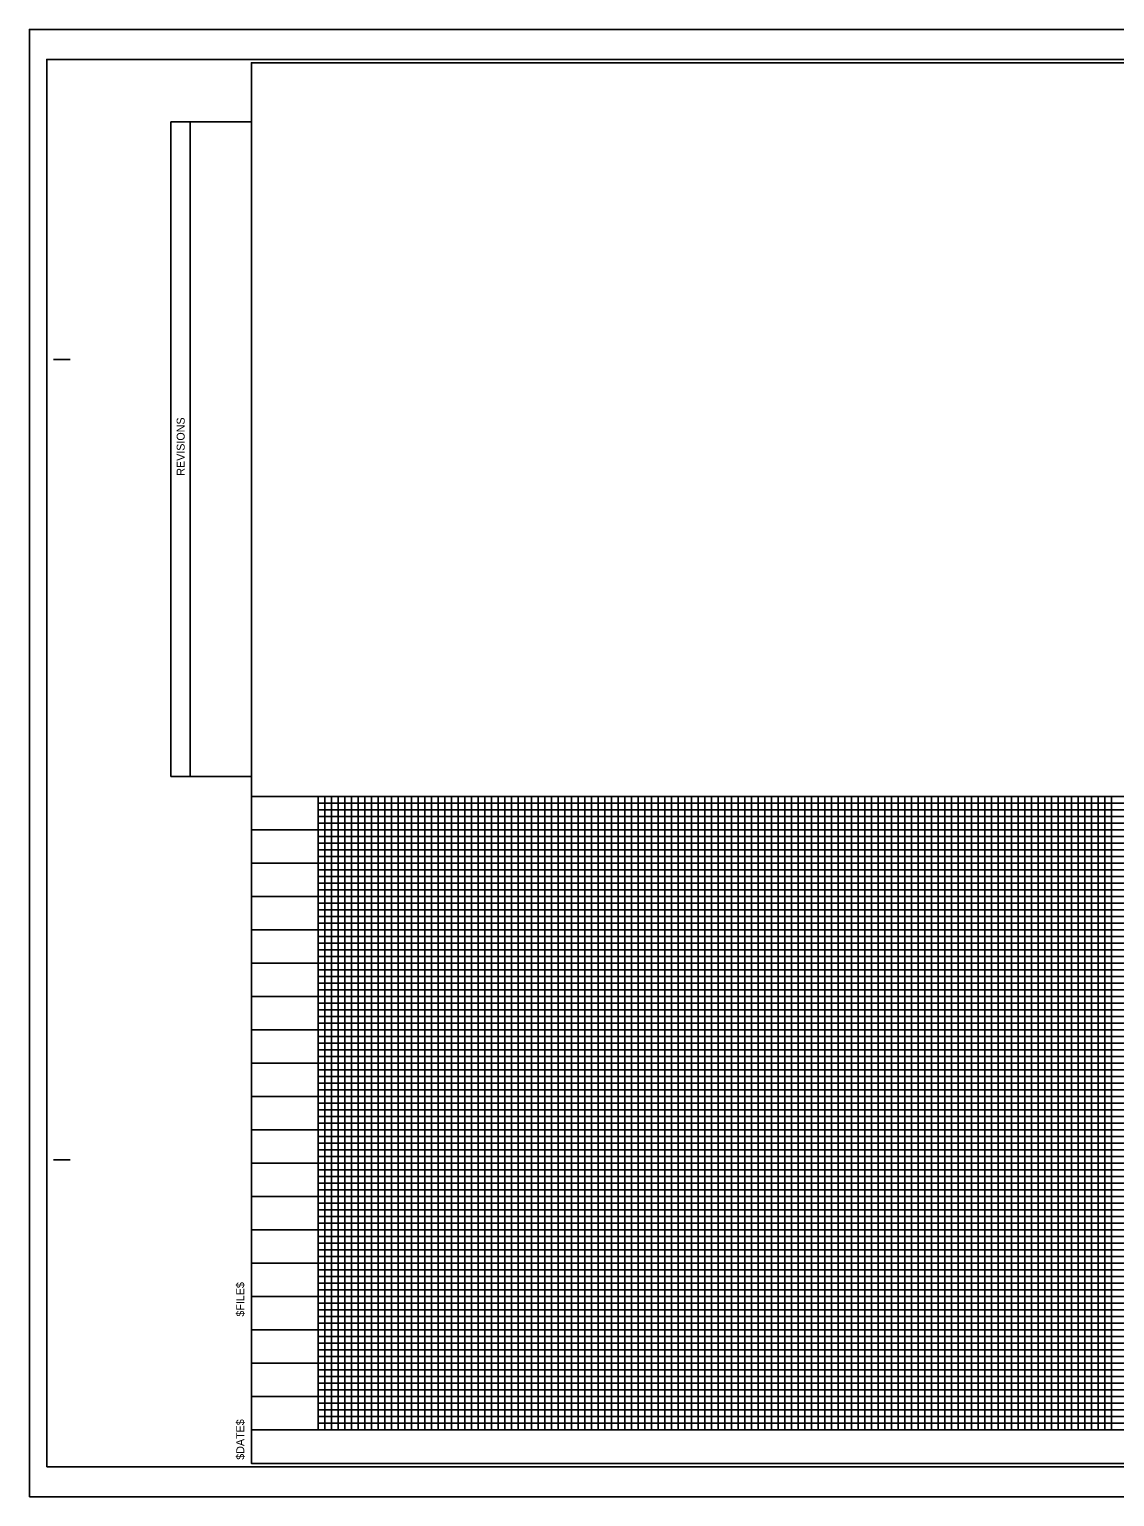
# Model space of a CAD drawing. Extents: x 2431000 to 2534000, y 645879 to 714000.
# Drawn here: x 2466103 to 2466917, y 671379 to 672479 of the extents above; entities that cross this region are included whole.
import ezdxf

# ---------------------------------------------------------------- set-up
doc = ezdxf.new("R2010")
doc.units = 0
for name, color, linetype in [('KHA_LOGO', 7, 'Continuous'), ('Prop Dimension', 7, 'Continuous'), ('Prop Dimension Text', 7, 'Continuous'), ('Prop Shade Light', 7, 'Continuous'), ('Prop Shade Medium', 7, 'Continuous'), ('Prop Terminator CELL', 7, 'Continuous'), ('Sheet Cross Section CELL', 7, 'Continuous'), ('Sheet Cross Section Grid Major CELL', 7, 'Continuous'), ('Sheet Cross Section Grid Minor 1 CELL', 7, 'Continuous'), ('Sheet Cross Section Grid Minor 2 CELL', 7, 'Continuous'), ('Sheet North Arrow Point CELL', 7, 'Continuous')]:
    doc.layers.add(name, color=color, linetype=linetype)

msp = doc.modelspace()

# ---------------------------------------------------------------- linework, layer by layer
at = {"layer": 'KHA_LOGO'}
for p, q in [((2466269.2, 672453.6), (2466269.2, 672453.6)), ((2466120.7, 672231.1), (2466133.2, 672231.1)), ((2466120.7, 671631.1), (2466133.2, 671631.1)), ((2466269.2, 671403.6), (2466269.2, 671403.6))]:
    msp.add_line(p, q, dxfattribs=at)
msp.add_lwpolyline([(2467769.2, 672453.6), (2466269.2, 672453.6), (2466269.2, 671403.6), (2467769.2, 671403.6)], close=True, dxfattribs=at)
at = {"layer": 'Prop Dimension'}
msp.add_lwpolyline([(2466102.7, 671378.6), (2467786.2, 671378.6), (2467786.2, 672478.6), (2466102.7, 672478.6)], close=True, dxfattribs=at)
at = {"layer": 'Prop Shade Light'}
for p, q in [((2466208.7, 671918.6), (2466208.7, 672409.3)), ((2466269.2, 672409.3), (2466208.7, 672409.3)), ((2466223.2, 671918.6), (2466223.2, 672409.3)), ((2466269.2, 671918.6), (2466208.7, 671918.6))]:
    msp.add_line(p, q, dxfattribs=at)
at = {"layer": 'Prop Shade Medium'}
for p, q in [((2466269.2, 671903.6), (2467769.2, 671903.6)), ((2466319.2, 671903.6), (2466319.2, 671428.6)), ((2466369.2, 671903.6), (2466369.2, 671428.6)), ((2466419.2, 671903.6), (2466419.2, 671428.6)), ((2466469.2, 671903.6), (2466469.2, 671428.6)), ((2466519.2, 671903.6), (2466519.2, 671428.6)), ((2466569.2, 671903.6), (2466569.2, 671428.6)), ((2466619.2, 671903.6), (2466619.2, 671428.6)), ((2466669.2, 671903.6), (2466669.2, 671428.6)), ((2466719.2, 671903.6), (2466719.2, 671428.6)), ((2466769.2, 671903.6), (2466769.2, 671428.6)), ((2466819.2, 671903.6), (2466819.2, 671428.6)), ((2466869.2, 671903.6), (2466869.2, 671428.6)), ((2466269.2, 671853.6), (2467769.2, 671853.6)), ((2466269.2, 671803.6), (2467769.2, 671803.6)), ((2466269.2, 671753.6), (2467769.2, 671753.6)), ((2466269.2, 671703.6), (2467769.2, 671703.6)), ((2466269.2, 671653.6), (2467769.2, 671653.6)), ((2466269.2, 671603.6), (2467769.2, 671603.6)), ((2466269.2, 671553.6), (2467769.2, 671553.6)), ((2466269.2, 671503.6), (2467769.2, 671503.6)), ((2466269.2, 671453.6), (2467769.2, 671453.6))]:
    msp.add_line(p, q, dxfattribs=at)
at = {"layer": 'Prop Terminator CELL'}
msp.add_lwpolyline([(2466115.7, 671401.1), (2467781.7, 671401.1), (2467781.7, 672456.1), (2466115.7, 672456.1)], close=True, dxfattribs=at)
at = {"layer": 'Sheet Cross Section CELL'}
for points in [[(2466324.2, 671428.6), (2466324.2, 671903.6), (2466329.2, 671903.6), (2466329.2, 671428.6)], [(2466334.2, 671428.6), (2466334.2, 671903.6), (2466339.2, 671903.6), (2466339.2, 671428.6)], [(2466349.2, 671428.6), (2466349.2, 671903.6), (2466354.2, 671903.6), (2466354.2, 671428.6)], [(2466359.2, 671428.6), (2466359.2, 671903.6), (2466364.2, 671903.6), (2466364.2, 671428.6)], [(2466374.2, 671428.6), (2466374.2, 671903.6), (2466379.2, 671903.6), (2466379.2, 671428.6)], [(2466384.2, 671428.6), (2466384.2, 671903.6), (2466389.2, 671903.6), (2466389.2, 671428.6)], [(2466399.2, 671428.6), (2466399.2, 671903.6), (2466404.2, 671903.6), (2466404.2, 671428.6)], [(2466409.2, 671428.6), (2466409.2, 671903.6), (2466414.2, 671903.6), (2466414.2, 671428.6)], [(2466424.2, 671428.6), (2466424.2, 671903.6), (2466429.2, 671903.6), (2466429.2, 671428.6)], [(2466434.2, 671428.6), (2466434.2, 671903.6), (2466439.2, 671903.6), (2466439.2, 671428.6)], [(2466449.2, 671428.6), (2466449.2, 671903.6), (2466454.2, 671903.6), (2466454.2, 671428.6)], [(2466459.2, 671428.6), (2466459.2, 671903.6), (2466464.2, 671903.6), (2466464.2, 671428.6)], [(2466474.2, 671428.6), (2466474.2, 671903.6), (2466479.2, 671903.6), (2466479.2, 671428.6)], [(2466484.2, 671428.6), (2466484.2, 671903.6), (2466489.2, 671903.6), (2466489.2, 671428.6)], [(2466499.2, 671428.6), (2466499.2, 671903.6), (2466504.2, 671903.6), (2466504.2, 671428.6)], [(2466509.2, 671428.6), (2466509.2, 671903.6), (2466514.2, 671903.6), (2466514.2, 671428.6)], [(2466524.2, 671428.6), (2466524.2, 671903.6), (2466529.2, 671903.6), (2466529.2, 671428.6)], [(2466534.2, 671428.6), (2466534.2, 671903.6), (2466539.2, 671903.6), (2466539.2, 671428.6)], [(2466549.2, 671428.6), (2466549.2, 671903.6), (2466554.2, 671903.6), (2466554.2, 671428.6)], [(2466559.2, 671428.6), (2466559.2, 671903.6), (2466564.2, 671903.6), (2466564.2, 671428.6)], [(2466574.2, 671428.6), (2466574.2, 671903.6), (2466579.2, 671903.6), (2466579.2, 671428.6)], [(2466584.2, 671428.6), (2466584.2, 671903.6), (2466589.2, 671903.6), (2466589.2, 671428.6)], [(2466599.2, 671428.6), (2466599.2, 671903.6), (2466604.2, 671903.6), (2466604.2, 671428.6)], [(2466609.2, 671428.6), (2466609.2, 671903.6), (2466614.2, 671903.6), (2466614.2, 671428.6)], [(2466624.2, 671428.6), (2466624.2, 671903.6), (2466629.2, 671903.6), (2466629.2, 671428.6)], [(2466634.2, 671428.6), (2466634.2, 671903.6), (2466639.2, 671903.6), (2466639.2, 671428.6)], [(2466649.2, 671428.6), (2466649.2, 671903.6), (2466654.2, 671903.6), (2466654.2, 671428.6)], [(2466659.2, 671428.6), (2466659.2, 671903.6), (2466664.2, 671903.6), (2466664.2, 671428.6)], [(2466674.2, 671428.6), (2466674.2, 671903.6), (2466679.2, 671903.6), (2466679.2, 671428.6)], [(2466684.2, 671428.6), (2466684.2, 671903.6), (2466689.2, 671903.6), (2466689.2, 671428.6)], [(2466699.2, 671428.6), (2466699.2, 671903.6), (2466704.2, 671903.6), (2466704.2, 671428.6)], [(2466709.2, 671428.6), (2466709.2, 671903.6), (2466714.2, 671903.6), (2466714.2, 671428.6)], [(2466724.2, 671428.6), (2466724.2, 671903.6), (2466729.2, 671903.6), (2466729.2, 671428.6)], [(2466734.2, 671428.6), (2466734.2, 671903.6), (2466739.2, 671903.6), (2466739.2, 671428.6)], [(2466749.2, 671428.6), (2466749.2, 671903.6), (2466754.2, 671903.6), (2466754.2, 671428.6)], [(2466759.2, 671428.6), (2466759.2, 671903.6), (2466764.2, 671903.6), (2466764.2, 671428.6)], [(2466774.2, 671428.6), (2466774.2, 671903.6), (2466779.2, 671903.6), (2466779.2, 671428.6)], [(2466784.2, 671428.6), (2466784.2, 671903.6), (2466789.2, 671903.6), (2466789.2, 671428.6)], [(2466799.2, 671428.6), (2466799.2, 671903.6), (2466804.2, 671903.6), (2466804.2, 671428.6)], [(2466809.2, 671428.6), (2466809.2, 671903.6), (2466814.2, 671903.6), (2466814.2, 671428.6)], [(2466824.2, 671428.6), (2466824.2, 671903.6), (2466829.2, 671903.6), (2466829.2, 671428.6)], [(2466834.2, 671428.6), (2466834.2, 671903.6), (2466839.2, 671903.6), (2466839.2, 671428.6)], [(2466849.2, 671428.6), (2466849.2, 671903.6), (2466854.2, 671903.6), (2466854.2, 671428.6)], [(2466859.2, 671428.6), (2466859.2, 671903.6), (2466864.2, 671903.6), (2466864.2, 671428.6)], [(2466874.2, 671428.6), (2466874.2, 671903.6), (2466879.2, 671903.6), (2466879.2, 671428.6)], [(2466884.2, 671428.6), (2466884.2, 671903.6), (2466889.2, 671903.6), (2466889.2, 671428.6)], [(2466899.2, 671428.6), (2466899.2, 671903.6), (2466904.2, 671903.6), (2466904.2, 671428.6)], [(2466909.2, 671428.6), (2466909.2, 671903.6), (2466914.2, 671903.6), (2466914.2, 671428.6)], [(2467719.2, 671898.6), (2466319.2, 671898.6)], [(2467719.2, 671888.6), (2466319.2, 671888.6), (2466319.2, 671893.6), (2467719.2, 671893.6)], [(2467719.2, 671873.6), (2466319.2, 671873.6), (2466319.2, 671878.6), (2466319.2, 671883.6), (2467719.2, 671883.6)], [(2467719.2, 671863.6), (2466319.2, 671863.6), (2466319.2, 671868.6), (2467719.2, 671868.6)], [(2467719.2, 671848.6), (2466319.2, 671848.6), (2466319.2, 671853.6), (2466319.2, 671858.6), (2467719.2, 671858.6)], [(2467719.2, 671838.6), (2466319.2, 671838.6), (2466319.2, 671843.6), (2467719.2, 671843.6)], [(2467719.2, 671823.6), (2466319.2, 671823.6), (2466319.2, 671828.6), (2466319.2, 671833.6), (2467719.2, 671833.6)], [(2467719.2, 671813.6), (2466319.2, 671813.6), (2466319.2, 671818.6), (2467719.2, 671818.6)], [(2466319.2, 671798.6), (2466319.2, 671803.6), (2466319.2, 671808.6), (2467719.2, 671808.6)], [(2467719.2, 671793.6), (2466319.2, 671793.6), (2466319.2, 671798.6), (2467719.2, 671798.6)], [(2467719.2, 671783.6), (2466319.2, 671783.6), (2466319.2, 671788.6), (2467719.2, 671788.6)], [(2467719.2, 671768.6), (2466319.2, 671768.6), (2466319.2, 671773.6), (2467719.2, 671773.6)], [(2467719.2, 671758.6), (2466319.2, 671758.6), (2466319.2, 671763.6), (2467719.2, 671763.6)], [(2467719.2, 671743.6), (2466319.2, 671743.6), (2466319.2, 671748.6), (2467719.2, 671748.6)], [(2467719.2, 671733.6), (2466319.2, 671733.6), (2466319.2, 671738.6), (2467719.2, 671738.6)], [(2467719.2, 671718.6), (2466319.2, 671718.6), (2466319.2, 671723.6), (2467719.2, 671723.6)], [(2467719.2, 671708.6), (2466319.2, 671708.6), (2466319.2, 671713.6), (2467719.2, 671713.6)], [(2467719.2, 671693.6), (2466319.2, 671693.6), (2466319.2, 671698.6), (2467719.2, 671698.6)], [(2467719.2, 671683.6), (2466319.2, 671683.6), (2466319.2, 671688.6), (2467719.2, 671688.6)], [(2467719.2, 671668.6), (2466319.2, 671668.6), (2466319.2, 671673.6), (2467719.2, 671673.6)], [(2467719.2, 671658.6), (2466319.2, 671658.6), (2466319.2, 671663.6), (2467719.2, 671663.6)], [(2467719.2, 671643.6), (2466319.2, 671643.6), (2466319.2, 671648.6), (2467719.2, 671648.6)], [(2467719.2, 671633.6), (2466319.2, 671633.6), (2466319.2, 671638.6), (2467719.2, 671638.6)], [(2467719.2, 671618.6), (2466319.2, 671618.6), (2466319.2, 671623.6), (2467719.2, 671623.6)], [(2467719.2, 671608.6), (2466319.2, 671608.6), (2466319.2, 671613.6), (2467719.2, 671613.6)], [(2467719.2, 671593.6), (2466319.2, 671593.6), (2466319.2, 671598.6), (2467719.2, 671598.6)], [(2467719.2, 671583.6), (2466319.2, 671583.6), (2466319.2, 671588.6), (2467719.2, 671588.6)], [(2467719.2, 671568.6), (2466319.2, 671568.6), (2466319.2, 671573.6), (2467719.2, 671573.6)], [(2467719.2, 671558.6), (2466319.2, 671558.6), (2466319.2, 671563.6), (2467719.2, 671563.6)], [(2467719.2, 671543.6), (2466319.2, 671543.6), (2466319.2, 671548.6), (2467719.2, 671548.6)], [(2467719.2, 671533.6), (2466319.2, 671533.6), (2466319.2, 671538.6), (2467719.2, 671538.6)], [(2467719.2, 671518.6), (2466319.2, 671518.6), (2466319.2, 671523.6), (2467719.2, 671523.6)], [(2467719.2, 671508.6), (2466319.2, 671508.6), (2466319.2, 671513.6), (2467719.2, 671513.6)], [(2466319.2, 671493.6), (2466319.2, 671498.6), (2467719.2, 671498.6)], [(2466319.2, 671433.6), (2467719.2, 671433.6), (2467719.2, 671438.6), (2466319.2, 671438.6), (2466319.2, 671443.6), (2467719.2, 671443.6), (2467719.2, 671448.6), (2466319.2, 671448.6), (2466319.2, 671453.6), (2466319.2, 671458.6), (2467719.2, 671458.6), (2467719.2, 671463.6), (2466319.2, 671463.6), (2466319.2, 671468.6), (2467719.2, 671468.6), (2467719.2, 671473.6), (2466319.2, 671473.6), (2466319.2, 671478.6), (2466319.2, 671483.6), (2467719.2, 671483.6), (2467719.2, 671488.6), (2466319.2, 671488.6), (2466319.2, 671493.6), (2467719.2, 671493.6)]]:
    msp.add_lwpolyline(points, dxfattribs=at)
at = {"layer": 'Sheet Cross Section Grid Major CELL'}
for p, q in [((2466269.2, 671878.6), (2467769.2, 671878.6)), ((2467769.2, 671828.6), (2466269.2, 671828.6)), ((2466269.2, 671828.6), (2466269.2, 671778.6)), ((2466269.2, 671778.6), (2467769.2, 671778.6)), ((2467769.2, 671728.6), (2466269.2, 671728.6)), ((2466269.2, 671728.6), (2466269.2, 671678.6)), ((2466269.2, 671678.6), (2467769.2, 671678.6)), ((2467769.2, 671628.6), (2466269.2, 671628.6)), ((2466269.2, 671628.6), (2466269.2, 671578.6)), ((2466269.2, 671578.6), (2467769.2, 671578.6)), ((2467769.2, 671528.6), (2466269.2, 671528.6)), ((2466269.2, 671528.6), (2466269.2, 671478.6)), ((2466269.2, 671478.6), (2467769.2, 671478.6))]:
    msp.add_line(p, q, dxfattribs=at)
for points in [[(2466344.2, 671428.6), (2466344.2, 671903.6), (2466394.2, 671903.6), (2466394.2, 671428.6)], [(2466444.2, 671428.6), (2466444.2, 671903.6), (2466494.2, 671903.6), (2466494.2, 671428.6)], [(2466544.2, 671428.6), (2466544.2, 671903.6), (2466594.2, 671903.6), (2466594.2, 671428.6)], [(2466644.2, 671428.6), (2466644.2, 671903.6), (2466694.2, 671903.6), (2466694.2, 671428.6)], [(2466744.2, 671428.6), (2466744.2, 671903.6), (2466794.2, 671903.6), (2466794.2, 671428.6)], [(2466844.2, 671428.6), (2466844.2, 671903.6), (2466894.2, 671903.6), (2466894.2, 671428.6)]]:
    msp.add_lwpolyline(points, dxfattribs=at)
at = {"layer": 'Sheet Cross Section Grid Minor 1 CELL'}
msp.add_lwpolyline([(2466319.2, 671903.6), (2467719.2, 671903.6), (2467719.2, 671428.6), (2466319.2, 671428.6)], close=True, dxfattribs=at)
at = {"layer": 'Sheet Cross Section Grid Minor 2 CELL'}
msp.add_line((2467769.2, 671428.6), (2466269.2, 671428.6), dxfattribs=at)
at = {"layer": 'Sheet North Arrow Point CELL'}
for points in [[(2466269.2, 671903.6), (2467769.2, 671903.6)], [(2466319.2, 671428.6), (2466319.2, 671903.6), (2466369.2, 671903.6), (2466369.2, 671428.6)], [(2466419.2, 671428.6), (2466419.2, 671903.6), (2466469.2, 671903.6), (2466469.2, 671428.6)], [(2466519.2, 671428.6), (2466519.2, 671903.6), (2466569.2, 671903.6), (2466569.2, 671428.6)], [(2466619.2, 671428.6), (2466619.2, 671903.6), (2466669.2, 671903.6), (2466669.2, 671428.6)], [(2466719.2, 671428.6), (2466719.2, 671903.6), (2466769.2, 671903.6), (2466769.2, 671428.6)], [(2466819.2, 671428.6), (2466819.2, 671903.6), (2466869.2, 671903.6), (2466869.2, 671428.6)], [(2467769.2, 671853.6), (2466269.2, 671853.6), (2466269.2, 671803.6), (2467769.2, 671803.6)], [(2467769.2, 671753.6), (2466269.2, 671753.6), (2466269.2, 671703.6), (2467769.2, 671703.6)], [(2467769.2, 671653.6), (2466269.2, 671653.6), (2466269.2, 671603.6), (2467769.2, 671603.6)], [(2467769.2, 671553.6), (2466269.2, 671553.6), (2466269.2, 671503.6), (2467769.2, 671503.6)], [(2467769.2, 671453.6), (2466269.2, 671453.6)]]:
    msp.add_lwpolyline(points, dxfattribs=at)

# ---------------------------------------------------------------- texts
at = {"layer": 'Prop Dimension Text'}
for s, p in [('$FILE$', (2466263.9, 671513.6)), ('$DATE$', (2466263.9, 671406.3))]:
    msp.add_text(s, height=6, rotation=90, dxfattribs=at).set_placement(p)
at = {"layer": 'Prop Shade Light'}
msp.add_text('REVISIONS', height=6, rotation=90, dxfattribs=at).set_placement((2466219.2, 672144))

doc.saveas('drawing.dxf')
